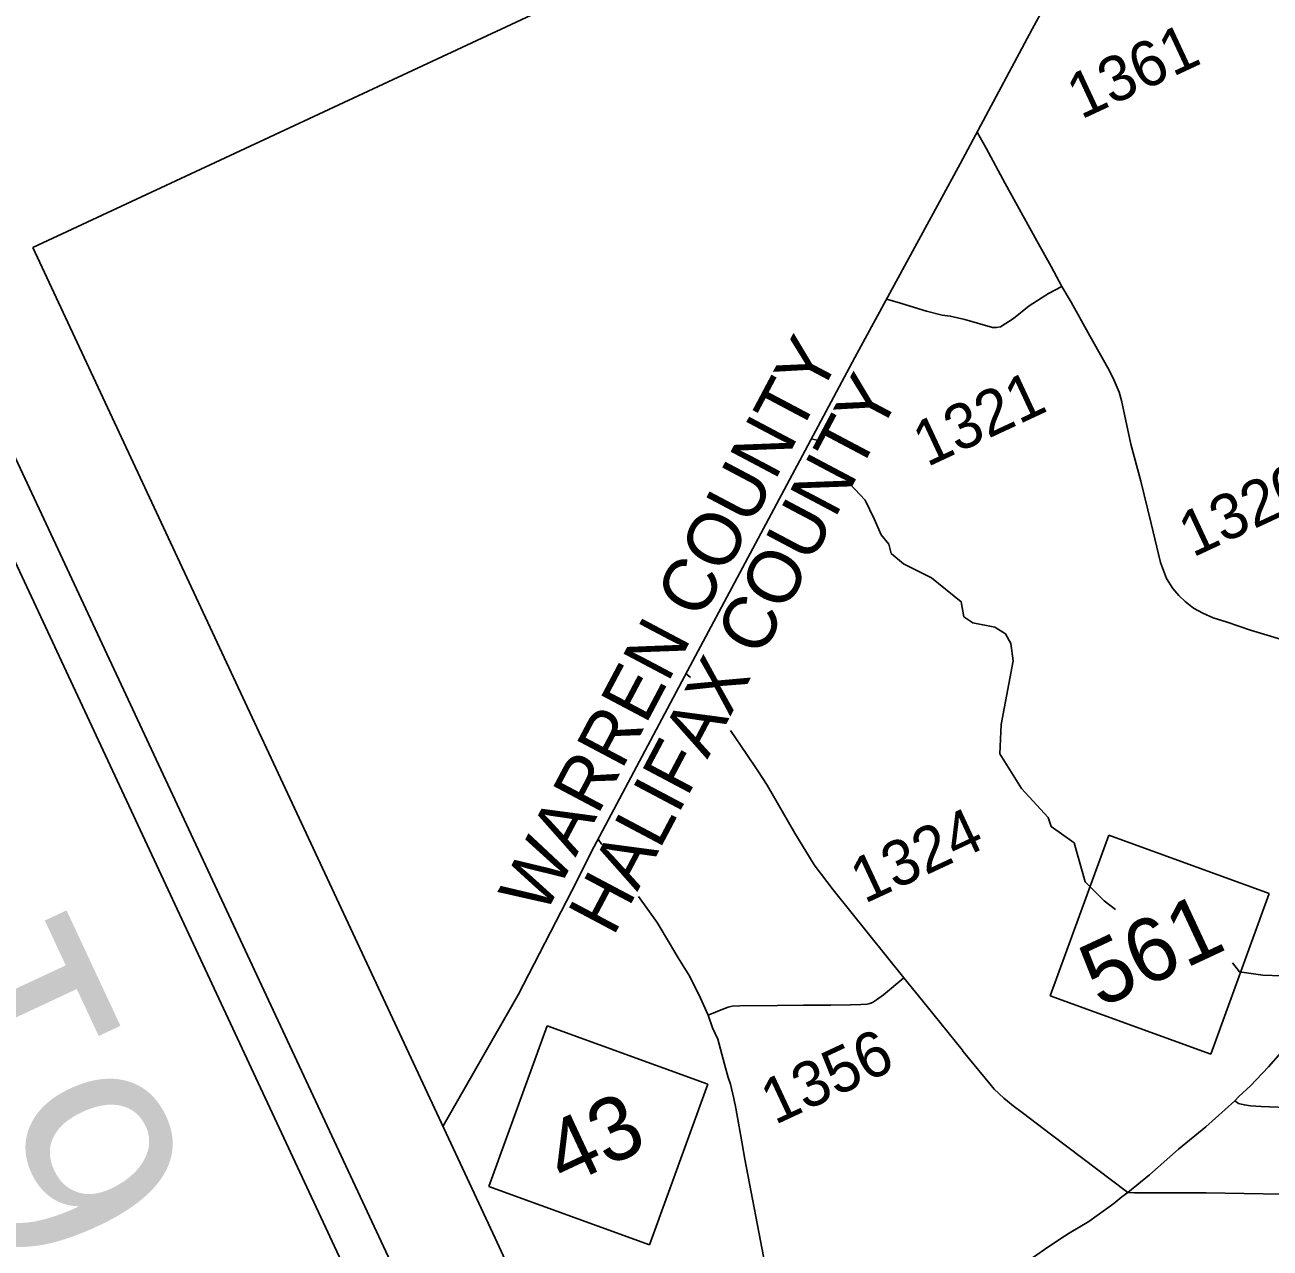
# Model space of a CAD drawing. Extents: x 2318983 to 2324558, y 920396 to 924651.
# Drawn here: x 2320104.6 to 2320442.5, y 922779.6 to 923111.6 of the extents above; entities that cross this region are included whole.
import ezdxf

# ---------------------------------------------------------------- set-up
doc = ezdxf.new("R2010")
doc.units = 0
for name, color, linetype in [('Exist Boundary Political CountyLine', 7, 'Continuous'), ('Exist Hydrographic Creek Single Shore', 7, 'Continuous'), ('Exist Road Primary NC Attributed', 7, 'Continuous'), ('Exist Road Primary NC Shield CELL', 7, 'Continuous'), ('Exist Road Primary NC Shield Number Label', 7, 'Continuous'), ('Exist Road Secondary Type 20 Attributed', 7, 'Continuous'), ('Exist Road Secondary Type 51 Attributed', 7, 'Continuous'), ('Exist Road Secondary Type 51 Number Label', 7, 'Continuous'), ('Pattern 3', 7, 'Continuous'), ('Sheet Data Field CELL', 7, 'Continuous'), ('Sheet Title CELL', 7, 'Continuous')]:
    doc.layers.add(name, color=color, linetype=linetype)

msp = doc.modelspace()

# ---------------------------------------------------------------- linework, layer by layer
at = {"layer": 'Exist Boundary Political CountyLine'}
msp.add_lwpolyline([(2320414.68, 923194.83), (2320410.98, 923178.95), (2320394.65, 923141.22), (2320377.91, 923110.4), (2320358.36, 923073.81), (2320329.75, 923021.28), (2320285.07, 922937.61), (2320259.09, 922888.55), (2320253.04, 922876.5), (2320238.46, 922848.27), (2320218.02, 922812.6)], dxfattribs=at)
at = {"layer": 'Exist Hydrographic Creek Single Shore'}
for points in [[(2320320.08, 922998.62), (2320319.56, 922998.88), (2320317.94, 922999.17)], [(2320400.49, 922871.46), (2320397.47, 922873.82), (2320392.28, 922878.94), (2320389.3, 922889.55), (2320383.1, 922893.98), (2320382.27, 922896.45), (2320375.01, 922904.31), (2320369.15, 922913.68), (2320369.5, 922921.69), (2320372.79, 922938.94), (2320372.13, 922943.68), (2320370.65, 922946.29), (2320367.77, 922948.1), (2320361.82, 922949.31), (2320359.34, 922950.91), (2320358.67, 922955), (2320350.62, 922961.45), (2320343, 922965.26), (2320339.68, 922968.11), (2320339.03, 922970.58), (2320336.97, 922973.17), (2320335.07, 922977.45), (2320332.56, 922982.59), (2320328.42, 922986.99)], [(2320522.93, 922909.18), (2320520.32, 922905.27), (2320511.76, 922900.88), (2320505.26, 922894.24), (2320500.17, 922890.96), (2320497.97, 922890.76), (2320495.95, 922891.18), (2320494.22, 922891.05), (2320492.48, 922890.83), (2320483, 922887.27), (2320475.05, 922882.26), (2320462.06, 922869.61), (2320459.03, 922865.45), (2320452.12, 922861.69), (2320445.65, 922853.43), (2320440.51, 922853.62), (2320434.16, 922854.57), (2320432.29, 922857)]]:
    msp.add_lwpolyline(points, dxfattribs=at)
at = {"layer": 'Exist Road Primary NC Attributed'}
for points in [[(2320261.11, 922889.12), (2320260.14, 922890.54)], [(2320290, 922842.81), (2320287.87, 922847.38), (2320285.01, 922853.23), (2320281.87, 922858.38), (2320279.53, 922862.29), (2320276.15, 922867.93), (2320271.11, 922875.03)], [(2320432.86, 922819.55), (2320434.02, 922820.69), (2320437.15, 922823.6), (2320442.08, 922828.76), (2320445.43, 922832.6), (2320449.23, 922836.86), (2320453.73, 922841.99), (2320459.42, 922848.69), (2320464.03, 922854.21), (2320469.54, 922860.53)], [(2320305.49, 922774.93), (2320299.94, 922803.69), (2320299.17, 922808.44), (2320297.5, 922817.55), (2320296.97, 922820.17), (2320296.07, 922824.04), (2320295.44, 922825.82), (2320294.41, 922829.44), (2320292.58, 922836.23), (2320291.21, 922839.3), (2320290, 922842.81)], [(2320403.89, 922794.66), (2320409.74, 922799.45), (2320417.64, 922806.37), (2320425, 922812.5), (2320432.86, 922819.55)], [(2320377.97, 922776.95), (2320382.43, 922780.03), (2320386.69, 922782.78), (2320387.91, 922783.58), (2320393.28, 922786.81), (2320400.09, 922791.67), (2320402.22, 922793.44), (2320403.89, 922794.66)]]:
    msp.add_lwpolyline(points, dxfattribs=at)
at = {"layer": 'Exist Road Primary NC Shield CELL'}
for p, q in [((2320382.84, 922848.04), (2320398.68, 922891.6)), ((2320398.68, 922891.6), (2320442.24, 922875.76)), ((2320442.24, 922875.76), (2320426.4, 922832.21)), ((2320426.4, 922832.21), (2320382.84, 922848.04)), ((2320230.48, 922796.31), (2320246.32, 922839.87)), ((2320246.32, 922839.87), (2320289.87, 922824.03)), ((2320289.87, 922824.03), (2320274.04, 922780.48)), ((2320274.04, 922780.48), (2320230.48, 922796.31))]:
    msp.add_line(p, q, dxfattribs=at)
at = {"layer": 'Exist Road Secondary Type 20 Attributed'}
msp.add_lwpolyline([(2320385.99, 923040.52), (2320382.34, 923038.63), (2320377.11, 923035.33), (2320372.82, 923031.88), (2320369.34, 923029.62), (2320368.16, 923029.39), (2320367.18, 923029.39), (2320359.63, 923031.56), (2320355.7, 923032.51), (2320353.51, 923032.77), (2320349.21, 923033.87), (2320341.28, 923036.31), (2320338.38, 923037.13)], dxfattribs=at)
at = {"layer": 'Exist Road Secondary Type 51 Attributed'}
for points in [[(2320385.99, 923040.52), (2320383.1, 923045.97), (2320379.2, 923052.99), (2320370.61, 923068.5), (2320365.46, 923078.13), (2320362.95, 923082.41)], [(2320449.22, 922943.66), (2320437.13, 922947.31), (2320430.81, 922949.41), (2320427.05, 922950.65), (2320424.19, 922951.85), (2320421.71, 922953.22), (2320419.45, 922955.07), (2320417.7, 922956.68), (2320416.06, 922958.6), (2320414.35, 922961.32), (2320412.71, 922965.65), (2320410.17, 922976.23), (2320407.41, 922987.68), (2320404.65, 922997.74), (2320402.11, 923009.61), (2320401.48, 923011.88), (2320400.19, 923015.02), (2320398.93, 923017.68), (2320393.52, 923027.17), (2320388.47, 923036.3), (2320385.99, 923040.52)], [(2320285.22, 922934.42), (2320284.5, 922935.07), (2320283.95, 922935.49)], [(2320343.06, 922852.95), (2320323.94, 922876.8), (2320318.78, 922883.58), (2320313.48, 922892.17), (2320308.7, 922900.54), (2320306.01, 922905.22), (2320303.43, 922909.13), (2320300.5, 922913.49), (2320296.04, 922920.01)], [(2320343.06, 922852.95), (2320337.55, 922848.31), (2320335.67, 922846.91), (2320334.55, 922846.25), (2320333.85, 922845.93), (2320333.15, 922845.79), (2320331.44, 922845.69), (2320328.58, 922845.62), (2320323.28, 922845.48), (2320322.04, 922845.49), (2320315.88, 922845.53), (2320308.84, 922845.43), (2320298.61, 922845.32), (2320296.52, 922845.18), (2320295.44, 922844.97), (2320294.01, 922844.45), (2320290, 922842.81)], [(2320403.89, 922794.66), (2320383.2, 922810.27), (2320375.21, 922816.35), (2320372.77, 922818.13), (2320371.2, 922819.45), (2320370.19, 922820.29), (2320367.63, 922822.7), (2320366.39, 922824.12), (2320359.23, 922832.95), (2320358.92, 922833.37), (2320349.41, 922845.13), (2320343.06, 922852.95)], [(2320432.86, 922819.55), (2320433.93, 922818.84), (2320434.59, 922818.64), (2320435.52, 922818.4), (2320437.13, 922818.15), (2320440.08, 922817.96), (2320446.86, 922817.73), (2320457.92, 922817.49), (2320460.05, 922817.45), (2320461.02, 922817.38), (2320461.58, 922817.24), (2320461.94, 922817.05), (2320462.22, 922816.59), (2320462.25, 922816.22), (2320462.23, 922815.59), (2320462.21, 922814.67), (2320462.07, 922808.51), (2320462, 922804.85), (2320461.79, 922796.89), (2320461.65, 922794.13)], [(2320403.89, 922794.66), (2320405.66, 922794.59), (2320406.82, 922794.6), (2320425.14, 922794.59), (2320456.12, 922794.03)]]:
    msp.add_lwpolyline(points, dxfattribs=at)
at = {"layer": 'Pattern 3'}
for p, q in [((2320106.71, 923051.1), (2320981.79, 923459.5)), ((2320232.17, 922782.28), (2320106.71, 923051.1)), ((2320401.68, 922419.08), (2320232.17, 922782.28))]:
    msp.add_line(p, q, dxfattribs=at)
at = {"layer": 'Sheet Title CELL'}
for p, q in [((2320909.23, 921264.35), (2320061.71, 923080.32)), ((2321086.13, 920856.94), (2320050.84, 923075.24))]:
    msp.add_line(p, q, dxfattribs=at)

# ---------------------------------------------------------------- texts
at = {"layer": 'Exist Road Primary NC Shield Number Label'}
for s, p in [('561', (2320396.31, 922844.59)), ('43', (2320250.9, 922796.1))]:
    msp.add_text(s, height=17.223, rotation=25.0187, dxfattribs=at).set_placement(p)
at = {"layer": 'Exist Road Secondary Type 51 Number Label'}
for s, p in [('1361', (2320391.17, 923085.79)), ('1321', (2320349.38, 922991.46)), ('1320', (2320421.48, 922966.91)), ('1324', (2320332.42, 922872.93)), ('1356', (2320308.09, 922812.9))]:
    msp.add_text(s, height=12.302, rotation=25.0187, dxfattribs=at).set_placement(p)
at = {"layer": 'Sheet Data Field CELL'}
for s, p in [('WARREN COUNTY', (2320245.48, 922869.41)), ('HALIFAX COUNTY', (2320264.24, 922863.86))]:
    msp.add_text(s, height=14.4, rotation=62.0938, dxfattribs=at).set_placement(p)
at = {"layer": 'Sheet Title CELL'}
msp.add_text(' B-4761  ', height=60, rotation=115.0187, dxfattribs=at).set_placement((2320233.08, 922620.13))

doc.saveas('drawing.dxf')
